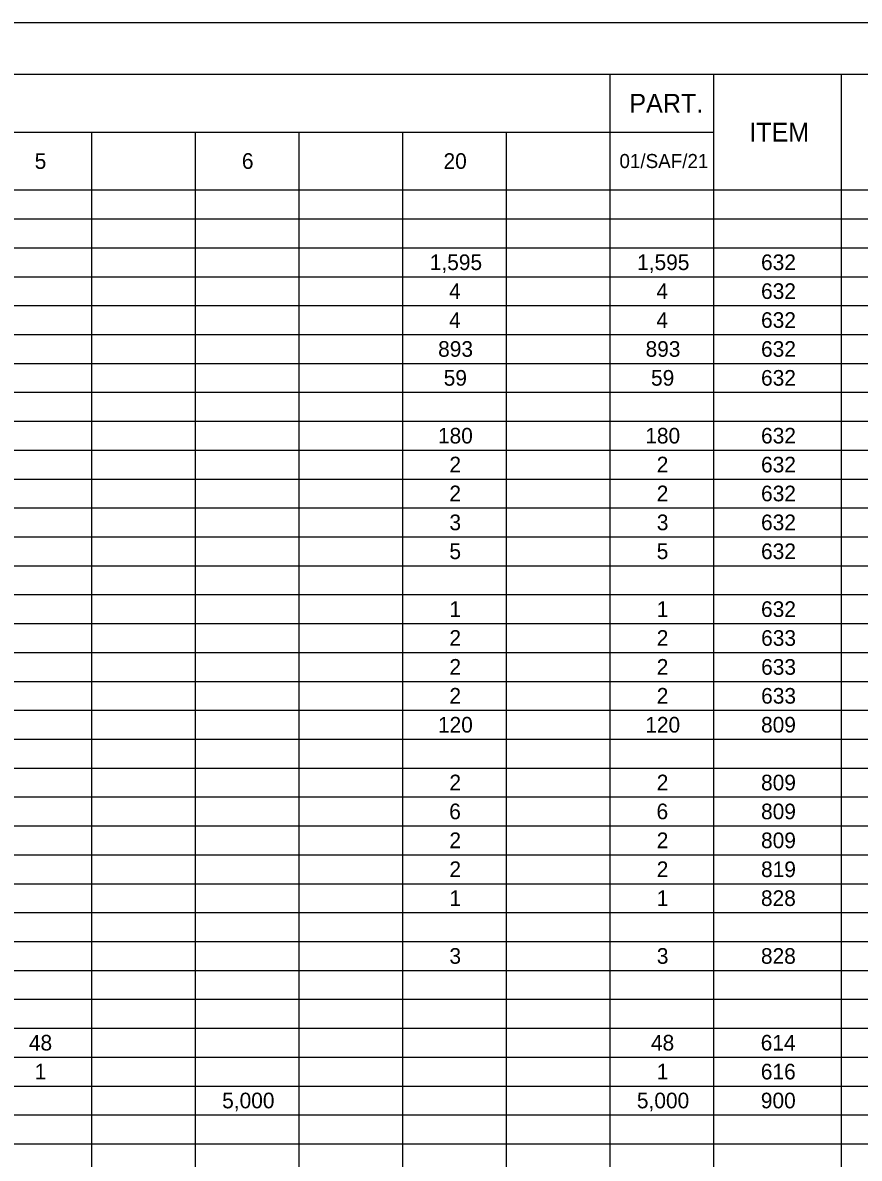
# Model space of a CAD drawing. Extents: x 0 to 34, y 0 to 22.
# Drawn here: x 8.87 to 16.98, y 11 to 22 of the extents above; entities that cross this region are included whole.
import ezdxf

# ---------------------------------------------------------------- set-up
doc = ezdxf.new("R2010")
doc.units = 0
for name, color, linetype in [('SH_Border', 7, 'Continuous'), ('SH_Cut_Line', 7, 'Continuous'), ('SH_Text', 7, 'Continuous')]:
    doc.layers.add(name, color=color, linetype=linetype)

msp = doc.modelspace()

# ---------------------------------------------------------------- linework, layer by layer
at = {"layer": 'SH_Border'}
msp.add_lwpolyline([(1.5, 21.5), (33.5, 21.5), (33.5, 0.5), (1.5, 0.5)], close=True, dxfattribs=at)
at = {"layer": 'SH_Cut_Line'}
msp.add_lwpolyline([(0, 0), (34, 0), (34, 22), (0, 22)], close=True, dxfattribs=at)
at = {"layer": 'SH_Text'}
for p, q in [((1.5, 21.5), (32.004, 21.5)), ((14.561, 21.5), (14.561, 0.5)), ((15.566, 21.5), (15.566, 0.5)), ((16.801, 21.5), (16.801, 0.5)), ((1.5, 20.94), (15.566, 20.94)), ((9.538, 20.94), (9.538, 0.5)), ((10.542, 20.94), (10.542, 0.5)), ((11.547, 20.94), (11.547, 0.5)), ((12.552, 20.94), (12.552, 0.5)), ((13.556, 20.94), (13.556, 0.5)), ((1.5, 20.38), (32.004, 20.38)), ((1.5, 20.1), (32.004, 20.1)), ((1.5, 19.82), (32.004, 19.82)), ((1.5, 19.54), (32.004, 19.54)), ((1.5, 19.26), (32.004, 19.26)), ((1.5, 18.98), (32.004, 18.98)), ((1.5, 18.7), (32.004, 18.7)), ((1.5, 18.42), (32.004, 18.42)), ((1.5, 18.14), (32.004, 18.14)), ((1.5, 17.86), (32.004, 17.86)), ((1.5, 17.58), (32.004, 17.58)), ((1.5, 17.3), (32.004, 17.3)), ((1.5, 17.02), (32.004, 17.02)), ((1.5, 16.74), (32.004, 16.74)), ((1.5, 16.46), (32.004, 16.46)), ((1.5, 16.18), (32.004, 16.18)), ((1.5, 15.9), (32.004, 15.9)), ((1.5, 15.62), (32.004, 15.62)), ((1.5, 15.34), (32.004, 15.34)), ((1.5, 15.06), (32.004, 15.06)), ((1.5, 14.78), (32.004, 14.78)), ((1.5, 14.5), (32.004, 14.5)), ((1.5, 14.22), (32.004, 14.22)), ((1.5, 13.94), (32.004, 13.94)), ((1.5, 13.66), (32.004, 13.66)), ((1.5, 13.38), (32.004, 13.38)), ((1.5, 13.1), (32.004, 13.1)), ((1.5, 12.82), (32.004, 12.82)), ((1.5, 12.54), (32.004, 12.54)), ((1.5, 12.26), (32.004, 12.26)), ((1.5, 11.98), (32.004, 11.98)), ((1.5, 11.7), (32.004, 11.7)), ((1.5, 11.42), (32.004, 11.42)), ((1.5, 11.14), (32.004, 11.14))]:
    msp.add_line(p, q, dxfattribs=at)

# ---------------------------------------------------------------- texts
for s, height, p in [('PART.', 0.1818, (14.75, 21.129)), ('ITEM', 0.1818, (15.912, 20.849)), ('5', 0.152, (8.987, 20.584)), ('6', 0.152, (10.995, 20.584)), ('20', 0.1515, (12.949, 20.584)), ('01/SAF/21', 0.1364, (14.654, 20.592)), ('1,595', 0.1515, (12.816, 19.604)), ('1,595', 0.1515, (14.825, 19.604)), ('632', 0.1515, (16.026, 19.604)), ('4', 0.152, (13.003, 19.324)), ('4', 0.152, (15.012, 19.324)), ('632', 0.1515, (16.026, 19.324)), ('4', 0.152, (13.003, 19.044)), ('4', 0.152, (15.012, 19.044)), ('632', 0.1515, (16.026, 19.044)), ('893', 0.1515, (12.897, 18.764)), ('893', 0.1515, (14.907, 18.764)), ('632', 0.1515, (16.026, 18.764)), ('59', 0.1515, (12.951, 18.484)), ('59', 0.1515, (14.96, 18.484)), ('632', 0.1515, (16.026, 18.484)), ('180', 0.1515, (12.895, 17.924)), ('180', 0.1515, (14.904, 17.924)), ('632', 0.1515, (16.026, 17.924)), ('2', 0.152, (13.006, 17.644)), ('2', 0.152, (15.015, 17.644)), ('632', 0.1515, (16.026, 17.644)), ('2', 0.152, (13.006, 17.364)), ('2', 0.152, (15.015, 17.364)), ('632', 0.1515, (16.026, 17.364)), ('3', 0.152, (13.006, 17.084)), ('3', 0.152, (15.016, 17.084)), ('632', 0.1515, (16.026, 17.084)), ('5', 0.152, (13.006, 16.804)), ('5', 0.152, (15.015, 16.804)), ('632', 0.1515, (16.026, 16.804)), ('1', 0.152, (13.006, 16.244)), ('1', 0.152, (15.015, 16.244)), ('632', 0.1515, (16.026, 16.244)), ('2', 0.152, (13.006, 15.964)), ('2', 0.152, (15.015, 15.964)), ('633', 0.1515, (16.027, 15.964)), ('2', 0.152, (13.006, 15.684)), ('2', 0.152, (15.015, 15.684)), ('633', 0.1515, (16.027, 15.684)), ('2', 0.152, (13.006, 15.404)), ('2', 0.152, (15.015, 15.404)), ('633', 0.1515, (16.027, 15.404)), ('120', 0.1515, (12.895, 15.124)), ('120', 0.1515, (14.904, 15.124)), ('809', 0.1515, (16.026, 15.124)), ('2', 0.152, (13.006, 14.564)), ('2', 0.152, (15.015, 14.564)), ('809', 0.1515, (16.026, 14.564)), ('6', 0.152, (13.004, 14.284)), ('6', 0.152, (15.013, 14.284)), ('809', 0.1515, (16.026, 14.284)), ('2', 0.152, (13.006, 14.004)), ('2', 0.152, (15.015, 14.004)), ('809', 0.1515, (16.026, 14.004)), ('2', 0.152, (13.006, 13.724)), ('2', 0.152, (15.015, 13.724)), ('819', 0.1515, (16.026, 13.724)), ('1', 0.152, (13.006, 13.444)), ('1', 0.152, (15.015, 13.444)), ('828', 0.1515, (16.025, 13.444)), ('3', 0.152, (13.006, 12.884)), ('3', 0.152, (15.016, 12.884)), ('828', 0.1515, (16.025, 12.884)), ('48', 0.1515, (8.931, 12.044)), ('48', 0.1515, (14.959, 12.044)), ('614', 0.1515, (16.023, 12.044)), ('1', 0.152, (8.987, 11.764)), ('1', 0.152, (15.015, 11.764)), ('616', 0.1515, (16.024, 11.764)), ('5,000', 0.1515, (10.804, 11.484)), ('5,000', 0.1515, (14.823, 11.484)), ('900', 0.1515, (16.024, 11.484))]:
    msp.add_text(s, height=height, dxfattribs=at).set_placement(p)

doc.saveas('drawing.dxf')
